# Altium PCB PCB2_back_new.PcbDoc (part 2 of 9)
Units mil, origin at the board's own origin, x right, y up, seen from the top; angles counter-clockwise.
Board outline 6299 x 3937 mil, 4 copper layers (TopLayer, GROUND, VCC, BottomLayer); 253 components, 421 nets, 2085 pads, 712 vias.
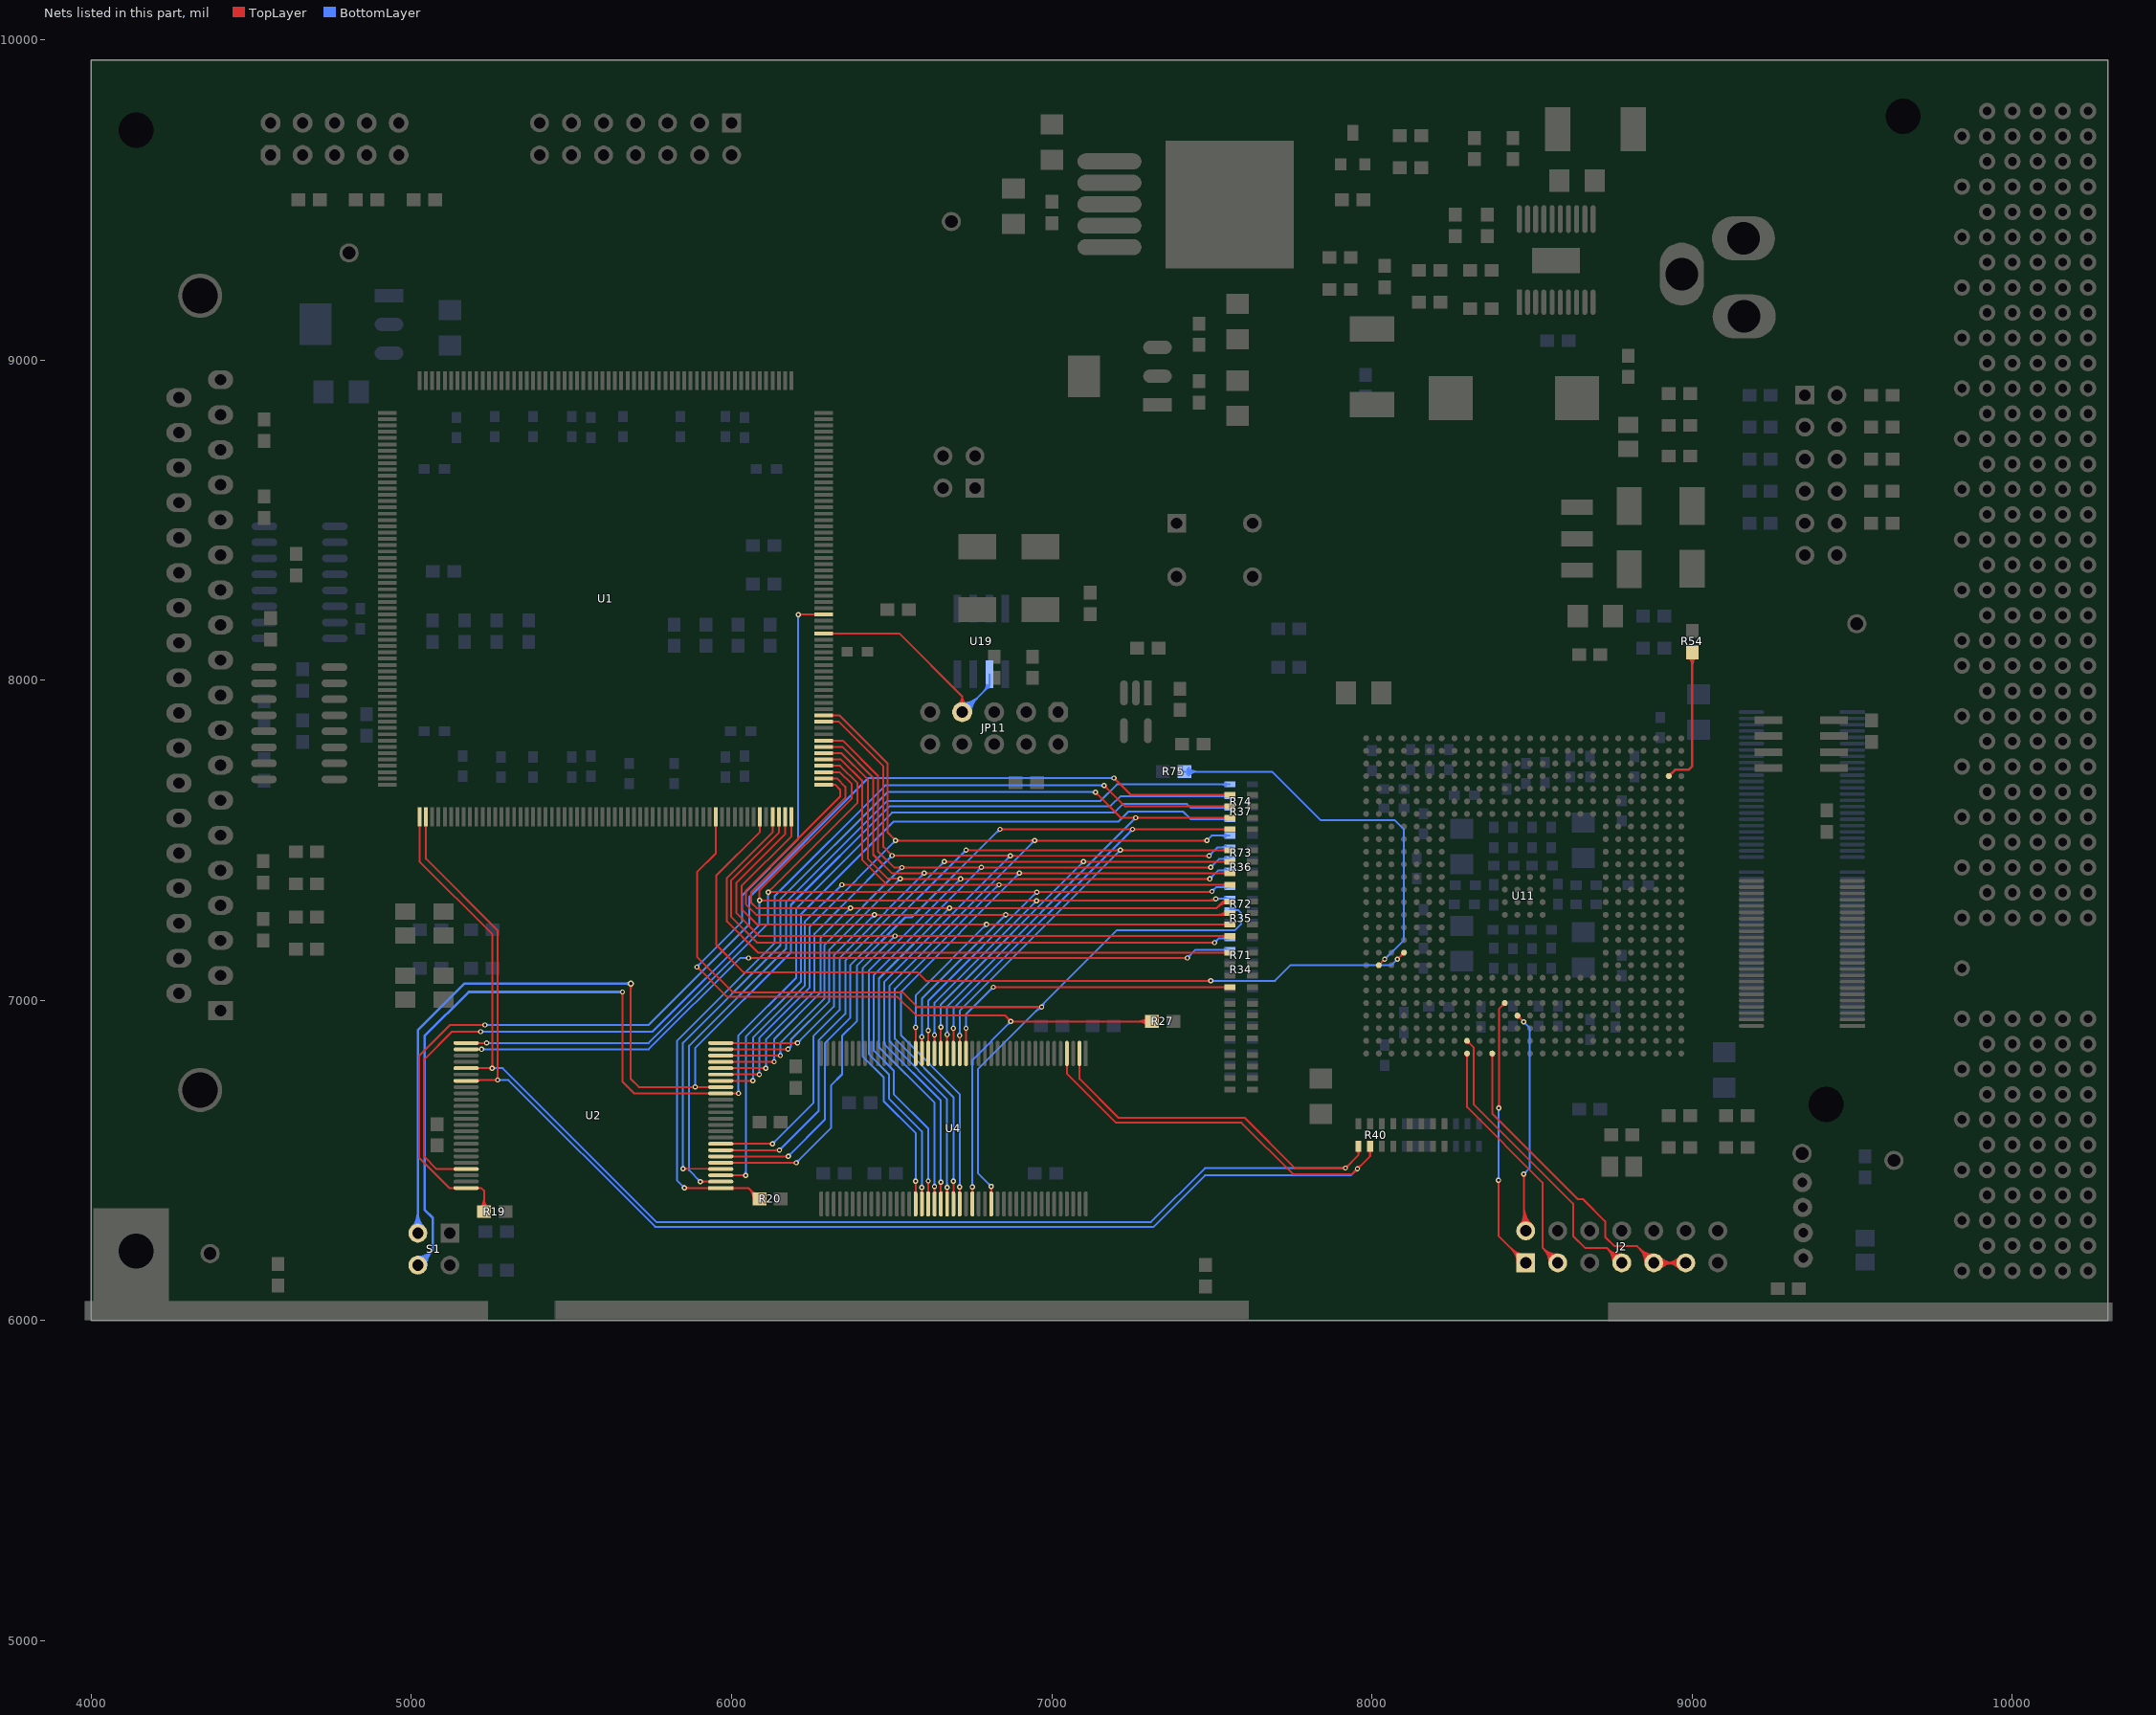
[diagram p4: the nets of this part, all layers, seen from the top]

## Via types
v1: diameter 16, hole 8, TopLayer to BottomLayer, 311 vias
v2: diameter 20, hole 10, TopLayer to BottomLayer, 202 vias
v3: diameter 24, hole 12, TopLayer to BottomLayer, 179 vias
v4: diameter 40, hole 20, TopLayer to BottomLayer, 12 vias
v5: diameter 30, hole 15, TopLayer to BottomLayer, 8 vias

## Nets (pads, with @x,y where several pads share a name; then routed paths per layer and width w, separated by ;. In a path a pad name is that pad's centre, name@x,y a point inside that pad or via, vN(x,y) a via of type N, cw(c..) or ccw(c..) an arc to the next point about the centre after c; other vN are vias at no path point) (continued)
BE1#: R72.6 U1.228 U4.71 | length 3283
  TopLayer w6: U1.228@5948.43,7547.22 cw(c5943.47,7542.26) 5950.49,7542.26 cw(c5957.5,7542.26) U1.228@5952.54,7547.22 ; U1.228@5950.49,7585.69 5950.49,7458.49 5892,7400 5892,7136 6003,7025 6534,7025 6580,6979 v1(6968,6979) ; v1@6807.19,6415.19 cw(c6798.65,6406.65) 6810.73,6406.65 cw(c6822.8,6406.65) v1@6814.26,6415.19 ; U4.71@6808.67,6399.52 ccw(c6803.71,6404.48) 6810.73,6404.48 ccw(c6817.74,6404.48) U4.71@6812.78,6399.52 ; U4.71@6810.73,6364 v1(6810.73,6418.73) ; v1@6964.46,6975.46 ccw(c6955.93,6966.93) 6955.93,6979 ccw(c6955.93,6991.07) v1@6964.46,6982.54
  BottomLayer w6: v1@6805.73,6418.73 ccw(c6793.65,6418.73) 6802.19,6427.26 ccw(c6810.73,6435.8) v1@6810.73,6423.72 ; v1@6816,6424 v1(6810.73,6418.73) 6770,6459.45 6770,6786 7203,7219 7572,7219 7591,7238 7591,7273 7582,7282 R72.6@7555.84,7282 ; 6950.93,6966.93 cw(c6968,6949.86) v1@6968,6974 ; v1@6973,6979 cw(c6997.14,6979) 6980.07,6996.07 ; R72.6@7568.59,7277.76 cw(c7578.83,7267.51) 7578.83,7282 cw(c7578.83,7296.49) R72.6@7568.59,7286.24
BE2#: R35.7 U1.240 U4.28 | length 2544.3
  TopLayer w6: U1.240@6184.65,7547.22 cw(c6179.69,7542.26) 6186.71,7542.26 cw(c6193.72,7542.26) U1.240@6188.76,7547.22 ; U1.240@6186.71,7585.69 6186.71,7512.71 6031,7357 6031,7285 6079,7237 R35.7@7555.84,7237 ; v1@6570.97,6911.97 cw(c6562.43,6903.43) 6574.51,6903.43 cw(c6586.58,6903.43) v1@6578.04,6911.97 ; U4.28@6572.45,6869.52 ccw(c6567.49,6874.48) 6574.51,6874.48 ccw(c6581.52,6874.48) U4.28@6576.56,6869.52 ; U4.28@6574.51,6834 v1(6574.51,6915.51) ; v1@6792.46,7233.46 ccw(c6783.93,7224.93) 6783.93,7237 ccw(c6783.93,7249.07) v1@6792.46,7240.54 ; v1@6799.54,7233.46 cw(c6808.07,7224.93) 6808.07,7237 cw(c6808.07,7249.07) v1@6799.54,7240.54 ; R35.7@7543.1,7232.76 ccw(c7532.86,7222.51) 7532.86,7237 ccw(c7532.86,7251.49) R35.7@7543.1,7241.24
  BottomLayer w6: v1@6570.97,6919.04 ccw(c6562.43,6927.58) 6574.51,6927.58 ccw(c6586.58,6927.58) v1@6578.04,6919.04 ; v1(6574.51,6915.51) 6574.51,7015.51 v1(6796,7237) ; v1@6791,7237 cw(c6778.93,7237) 6787.46,7228.46 cw(c6796,7219.93) v1@6796,7232
BE3#: R35.8 U1.239 U4.59 | length 3034.7
  TopLayer w6: U1.239@6164.97,7547.22 cw(c6160.01,7542.26) 6167.02,7542.26 cw(c6174.04,7542.26) U1.239@6169.08,7547.22 ; U1.239@6167.02,7585.69 6167.02,7519.02 6014,7366 6014,7273 6086,7201 R35.8@7555.84,7201 ; v1@6506.46,7197.46 ccw(c6497.93,7188.93) 6497.93,7201 ccw(c6497.93,7213.07) v1@6506.46,7204.54 ; v1@6513.54,7197.46 cw(c6522.07,7188.93) 6522.07,7201 cw(c6522.07,7213.07) v1@6513.54,7204.54 ; v1@6570.97,6431.97 cw(c6562.43,6423.43) 6574.51,6423.43 cw(c6586.58,6423.43) v1@6578.04,6431.97 ; U4.59@6572.45,6399.52 ccw(c6567.49,6404.48) 6574.51,6404.48 ccw(c6581.52,6404.48) U4.59@6576.56,6399.52 ; U4.59@6574.51,6364 v1(6574.51,6435.51) ; R35.8@7543.1,7196.76 ccw(c7532.86,7186.51) 7532.86,7201 ccw(c7532.86,7215.49) R35.8@7543.1,7205.24
  BottomLayer w6: v1@6505,7201 cw(c6492.93,7201) 6501.46,7192.46 cw(c6510,7183.93) v1@6510,7196 ; v1(6510,7201) 6409,7100 6409,6825 6475,6759 6475,6685 6574.51,6585.49 v1(6574.51,6435.51) ; v1@6570.97,6439.04 ccw(c6562.43,6447.58) 6574.51,6447.58 ccw(c6586.58,6447.58) v1@6578.04,6439.04
CE0#: R34.8 U4.20 | length 1090.7
  TopLayer w6: v1@6728.45,6908.78 cw(c6719.91,6900.24) 6731.98,6900.24 cw(c6744.06,6900.24) v1@6735.52,6908.78 ; U4.20@6729.93,6869.52 ccw(c6724.97,6874.48) 6731.99,6874.48 ccw(c6739,6874.48) U4.20@6734.04,6869.52 ; U4.20@6731.98,6834 v1(6731.98,6912.31) ; v1(6817,7041) R34.8@7555.84,7041 ; v1@6820.54,7037.46 cw(c6829.07,7028.93) 6829.07,7041 cw(c6829.07,7053.07) v1@6820.54,7044.54 ; R34.8@7543.1,7036.76 ccw(c7532.86,7026.51) 7532.86,7041 ccw(c7532.86,7055.49) R34.8@7543.1,7045.24
  BottomLayer w6: v1@6728.45,6915.85 ccw(c6719.91,6924.39) 6731.98,6924.39 ccw(c6744.06,6924.39) v1@6735.52,6915.85 ; v1(6731.98,6912.31) 6731.98,6955.98 v1(6817,7041) ; v1@6812,7041 cw(c6799.93,7041) 6808.46,7032.46 cw(c6817,7023.93) v1@6817,7036
CE1#: R71.7 U2.26 | length 2661.4
  TopLayer w6: U2.26@5170.72,6847.07 v1(5219,6847) ; U2.26@5206.24,6845.01 cw(c5211.08,6840.16) v1@5211.09,6847.01 ; U2.26@5206.25,6849.12 ccw(c5211.33,6854.19) v1@5211.32,6847.01 ; v1@5215.46,6843.47 ccw(c5206.91,6834.95) 5206.93,6847.02 ccw(c5206.95,6859.09) v1@5215.47,6850.54 ; v1(6053,7132) v1(7423,7132) ; v1@6056.54,7128.46 cw(c6065.07,7119.93) 6065.07,7132 cw(c6065.07,7144.07) v1@6056.54,7135.54 ; v1@7419.46,7128.46 ccw(c7410.93,7119.93) 7410.93,7132 ccw(c7410.93,7144.07) v1@7419.46,7135.54
  BottomLayer w6: v1(5219,6847) 5576.07,6847.07 5741.07,6847.07 6026,7132 v1(6053,7132) ; v1@5222.54,6843.47 cw(c5231.07,6834.93) 5231.07,6847 cw(c5231.07,6859.07) v1@5222.53,6850.54 ; v1@6049.46,7128.46 ccw(c6040.93,7119.93) 6040.93,7132 ccw(c6040.93,7144.07) v1@6049.46,7135.54 ; v1(7423,7132) 7449,7158 R71.7@7555.84,7158 ; v1@7423,7137 ccw(c7423,7149.07) 7431.54,7140.54 ccw(c7440.07,7132) v1@7428,7132 ; R71.7@7543.1,7153.76 ccw(c7532.86,7143.51) 7532.86,7158 ccw(c7532.86,7172.49) R71.7@7543.1,7162.24
CE2#: R71.8 U1.238 | length 2054.9
  TopLayer w6: U1.238@6145.28,7547.22 cw(c6140.32,7542.26) 6147.34,7542.26 cw(c6154.35,7542.26) U1.238@6149.39,7547.22 ; U1.238@6147.34,7585.69 6147.34,7523.34 5998,7374 5998,7262 6080,7180 v1(7508,7180) ; v1@7504.46,7176.46 ccw(c7495.93,7167.93) 7495.93,7180 ccw(c7495.93,7192.07) v1@7504.46,7183.54
  BottomLayer w6: v1(7508,7180) 7522,7194 R71.8@7555.84,7194 ; v1@7508,7185 ccw(c7508,7197.07) 7516.54,7188.54 ccw(c7525.07,7180) v1@7513,7180 ; R71.8@7543.1,7189.76 ccw(c7532.86,7179.51) 7532.86,7194 ccw(c7532.86,7208.49) R71.8@7543.1,7198.24
CE3#: R34.5 U1.237 | length 2043.6
  TopLayer w6: U1.237@6125.6,7547.22 cw(c6120.64,7542.26) 6127.65,7542.26 cw(c6134.67,7542.26) U1.237@6129.71,7547.22 ; U1.237@6127.65,7585.69 6127.65,7524.65 5985,7382 5985,7246 6082,7149 R34.5@7555.84,7149 ; R34.5@7543.1,7144.76 ccw(c7532.86,7134.51) 7532.86,7149 ccw(c7532.86,7163.49) R34.5@7543.1,7153.24
DATA: JP11.7 U1.25 U19.2 | length 1133
  TopLayer w6: U1.25@6287.1,8145.73 6523.27,8145.73 6720,7949 ; U1.25@6312.78,8143.68 cw(c6317.74,8138.72) 6317.74,8145.73 cw(c6317.74,8152.75) U1.25@6312.78,8147.79 ; JP11.7@6705.79,7924.12 ccw(c6691.13,7949) 6720,7949 ; JP11.7@6708.83,7918.95 ccw(c6697.32,7938.5) 6720,7938.5 ccw(c6742.68,7938.5) JP11.7@6731.17,7918.95 ; JP11.7@6720,7900 6720,7949 ; JP11.7@6734.21,7924.12 cw(c6748.87,7949) 6720,7949
  BottomLayer w6: JP11.7@6720,7900 6723,7900 6805,7982 U19.2@6805,8017.64 ; JP11.7@6720,7916 ccw(c6720,7961.87) 6752.44,7929.44 ; JP11.7@6720,7922 ccw(c6720,7982.36) 6762.68,7939.68 ; JP11.7@6720,7928 ccw(c6720,8002.84) 6772.92,7949.92 ; JP11.7@6736,7900 cw(c6767.38,7900) 6745.19,7922.19 ; JP11.7@6742,7900 cw(c6787.87,7900) 6755.44,7932.44 ; JP11.7@6748,7900 cw(c6808.36,7900) 6765.68,7942.68 ; 6787.03,7964.03 ccw(c6764.92,7986.14) U19.2@6796.19,7986.14 ; 6797.03,7974.03 cw(c6805,7966.06) U19.2@6805,7977.33 ; 6797.27,7974.27 ccw(c6785.4,7986.14) U19.2@6802.19,7986.14
DSP_CLKIN: R54.2 U11.AC2 | length 521.1
  TopLayer w8: U11.AC2@8926.63,7700.14 8946.49,7720 8989,7720 9000,7731 R54.2@9000,8086.54 ; U11.AC2@8926.63,7705.39 ccw(c8926.63,7718.07) 8935.6,7709.11 ccw(c8944.56,7700.14) U11.AC2@8931.88,7700.14 ; R54.2@8988.91,8073.48 cw(c8962.13,8046.7) 9000,8046.7 cw(c9037.87,8046.7) R54.2@9011.09,8073.48
DSP_T\R\S\T\: J2.2 U11.D14 | length 1013.7
  TopLayer w6: U11.D14@8454.19,6945.86 cw(c8454.19,6930.77) 8464.86,6941.44 cw(c8475.53,6952.11) U11.D14@8460.44,6952.11 ; U11.D14@8454.19,6952.11 v1(8474,6932.3) ; J2.2@8461.24,6298.76 ccw(c8430.44,6329.56) 8474,6329.56 ccw(c8529.56,6329.56) J2.2@8490.27,6290.27 ; J2.2@8465.48,6294.52 ccw(c8444.93,6315.07) 8474,6315.07 ccw(c8515.07,6315.07) J2.2@8486.03,6286.03 ; v1@8470.46,6453.46 cw(c8461.93,6444.93) 8474,6444.93 cw(c8486.07,6444.93) v1@8477.54,6453.46 ; 8474,6344.04 ccw(c8544.04,6344.04) J2.2@8494.52,6294.52 ; 8474,6358.53 ccw(c8558.53,6358.53) J2.2@8498.76,6298.76 ; v1(8474,6457) 8474,6286 J2.2@8480,6280
  BottomLayer w6: v1(8474,6457) 8492,6475 8492,6914.3 v1(8474,6932.3) ; v1@8474,6462 ccw(c8474,6474.07) 8482.54,6465.54 ccw(c8491.07,6457) v1@8479,6457
DSP_TCLK: J2.9 J2.11 U11.A16 | length 1738.3
  TopLayer w6: U11.A16@8371.03,6829.58 cw(c8360.36,6818.91) 8375.45,6818.91 cw(c8390.54,6818.91) U11.A16@8379.87,6829.58 ; U11.A16@8375.45,6834 8375.45,6646.55 8643,6379 8659,6379 8728,6310 8728,6261 8757,6232 8828,6232 J2.9@8880,6180 J2.11@8980,6180 ; J2.9@8853.47,6180 ccw(c8789.43,6180) 8834.71,6225.29 ccw(c8880,6270.57) J2.9@8880,6206.53 ; J2.9@8859.47,6180 ccw(c8809.91,6180) 8844.96,6215.04 ccw(c8880,6250.09) J2.9@8880,6200.53 ; J2.9@8865.47,6180 ccw(c8830.4,6180) 8855.2,6204.8 ccw(c8880,6229.6) J2.9@8880,6194.53 ; J2.9@8890.27,6169.73 cw(c8915.07,6144.93) 8915.07,6180 cw(c8915.07,6215.07) J2.9@8890.27,6190.27 ; J2.9@8894.52,6165.48 cw(c8929.56,6130.44) 8929.56,6180 cw(c8929.56,6229.56) J2.9@8894.52,6194.52 ; J2.9@8898.76,6161.24 cw(c8944.04,6115.96) 8944.04,6180 cw(c8944.04,6244.04) J2.9@8898.76,6198.76 ; J2.11@8961.24,6161.24 ccw(c8915.96,6115.96) 8915.96,6180 ccw(c8915.96,6244.04) J2.11@8961.24,6198.76 ; J2.11@8965.48,6165.48 ccw(c8930.44,6130.44) 8930.44,6180 ccw(c8930.44,6229.56) J2.11@8965.48,6194.52 ; J2.11@8969.73,6169.73 ccw(c8944.93,6144.93) 8944.93,6180 ccw(c8944.93,6215.07) J2.11@8969.73,6190.27
DSP_TDI: J2.3 U11.A18 | length 1028.6
  TopLayer w6: U11.A18@8292.29,6829.58 cw(c8281.61,6818.91) 8296.71,6818.91 cw(c8311.8,6818.91) U11.A18@8301.13,6829.58 ; U11.A18@8296.71,6834 8296.71,6666.29 8532,6431 8532,6228 J2.3@8580,6180 ; J2.3@8553.47,6180 ccw(c8489.43,6180) 8534.71,6225.29 ccw(c8580,6270.57) J2.3@8580,6206.53 ; J2.3@8559.47,6180 ccw(c8509.91,6180) 8544.96,6215.04 ccw(c8580,6250.09) J2.3@8580,6200.53 ; J2.3@8565.47,6180 ccw(c8530.4,6180) 8555.2,6204.8 ccw(c8580,6229.6) J2.3@8580,6194.53
DSP_TDO: J2.7 U11.B18 | length 1190.6
  TopLayer w6: U11.B18@8296.71,6867.12 cw(c8296.71,6852.02) 8307.38,6862.7 cw(c8318.05,6873.37) U11.B18@8302.96,6873.37 ; U11.B18@8296.71,6873.37 8317,6853.08 8317,6676 8628,6365 8628,6264 8666,6226 8734,6226 J2.7@8780,6180 ; J2.7@8753.47,6180 ccw(c8689.43,6180) 8734.71,6225.29 ccw(c8780,6270.57) J2.7@8780,6206.53 ; J2.7@8759.47,6180 ccw(c8709.91,6180) 8744.96,6215.04 ccw(c8780,6250.09) J2.7@8780,6200.53 ; J2.7@8765.47,6180 ccw(c8730.4,6180) 8755.2,6204.8 ccw(c8780,6229.6) J2.7@8780,6194.53
DSP_TMS: J2.1 U11.E15 | length 1188
  TopLayer w6: v1@8391.46,6434.46 cw(c8382.93,6425.93) 8395,6425.93 cw(c8407.07,6425.93) v1@8398.54,6434.46 ; v1@8392.46,6667.54 ccw(c8383.93,6676.07) 8396,6676.07 ccw(c8408.07,6676.07) v1@8399.54,6667.54 ; v1(8395,6438) 8395,6265 J2.1@8480,6180 ; v1(8396,6664) 8396,6972.66 U11.E15@8414.82,6991.48 ; U11.E15@8408.57,6991.48 cw(c8393.47,6991.48) 8404.15,6980.81 cw(c8414.82,6970.14) U11.E15@8414.82,6985.23 ; J2.1@8453.47,6180 ccw(c8389.43,6180) 8434.71,6225.29 ccw(c8480,6270.57) J2.1@8480,6206.53 ; J2.1@8459.47,6180 ccw(c8409.91,6180) 8444.96,6215.04 ccw(c8480,6250.09) J2.1@8480,6200.53 ; J2.1@8465.47,6180 ccw(c8430.4,6180) 8455.2,6204.8 ccw(c8480,6229.6) J2.1@8480,6194.53
  BottomLayer w6: v1@8391.46,6441.54 ccw(c8382.93,6450.07) 8395,6450.07 ccw(c8407.07,6450.07) v1@8398.54,6441.54 ; v1@8392.46,6660.46 cw(c8386.34,6654.34) 8395,6654.34 ; v1(8395,6438) 8395,6663 v1(8396,6664) ; 8395,6649.51 cw(c8410.49,6649.51) v1@8399.54,6660.46
EA03: R72.7 U1.3 U2.45 U4.25 | length 4739.6
  TopLayer w6: U2.45@5135.21,6471 ccw(c5130.25,6466.04) 5130.25,6473.06 ccw(c5130.25,6480.07) U2.45@5135.21,6475.11 ; U2.45@5170.72,6473.06 5078.94,6473.06 5039,6513 5039,6815 5126,6902 v1(5216,6902) ; v1@5212.46,6898.46 ccw(c5203.93,6889.93) 5203.93,6902 ccw(c5203.93,6914.07) v1@5212.46,6905.54 ; v1@6083.46,7315.54 ccw(c6074.93,7324.07) 6087,7324.07 ccw(c6099.07,7324.07) 6090.54,7315.54 ccw(c6101.49,7326.49) 6101.49,7311 ; v1(6087,7312) 6087,7343 6375,7631 6375,7675 6337.34,7712.66 U1.3@6274.31,7712.66 ; v1@6088,7311 7506,7311 ; v1@6090.54,7308.46 cw(c6096.66,7302.34) 6096.66,7311 ; U1.3@6312.78,7710.61 cw(c6317.74,7705.65) 6317.74,7712.66 cw(c6317.74,7719.68) U1.3@6312.78,7714.72 ; v1@6630.02,6888.02 cw(c6621.49,6879.49) 6633.56,6879.49 cw(c6645.63,6879.49) v1@6637.1,6888.02 ; U4.25@6631.51,6869.52 ccw(c6626.55,6874.48) 6633.56,6874.48 ccw(c6640.57,6874.48) U4.25@6635.61,6869.52 ; U4.25@6633.56,6834 v1(6633.56,6891.56) ; v1@6948.46,7307.46 ccw(c6939.93,7298.93) 6939.93,7311 ccw(c6939.93,7323.07) v1@6948.46,7314.54 ; v1@6955.54,7307.46 cw(c6964.07,7298.93) 6964.07,7311 cw(c6964.07,7323.07) v1@6955.54,7314.54 ; 7485.44,7311 ccw(c7485.44,7343.56) v1@7508.46,7320.54 ; 7499.93,7311 ccw(c7499.93,7329.07) v1@7512.71,7316.29 ; v1@7507.19,7315.62 cw(c7502.68,7314.32) 7506,7311 ; v1@7510.62,7312.19 ccw(c7509.32,7307.68) 7506,7311 ; v1(7512,7317) 7506,7311
  BottomLayer w6: v1(5216,6902) 5753,6902 6087,7236 v1(6087,7312) ; v1@5219.54,6898.46 cw(c5228.07,6889.93) 5228.07,6902 cw(c5228.07,6914.07) v1@5219.54,6905.54 ; v1@6083.46,7308.46 cw(c6074.93,7299.93) 6087,7299.93 cw(c6099.07,7299.93) v1@6090.54,7308.46 ; v1@6630.02,6895.1 ccw(c6621.49,6903.63) 6633.56,6903.63 ccw(c6645.63,6903.63) v1@6637.1,6895.1 ; v1(6633.56,6891.56) 6633.56,6992.56 v1(6952,7311) ; v1@6947,7311 cw(c6934.93,7311) 6943.46,7302.46 cw(c6952,7293.93) v1@6952,7306 ; v1(7512,7317) R72.7@7554.84,7317 ; v1@7515.54,7313.46 cw(c7524.07,7304.93) 7524.07,7317 cw(c7524.07,7329.07) v1@7515.54,7320.54 ; 7530.44,7317 ccw(c7530.44,7334.9) R72.7@7543.1,7322.24 ; 7535.27,7317 cw(c7535.27,7305.93) R72.7@7543.1,7313.76
EA04: R72.8 U1.4 U2.25 U4.26 | length 4164.8
  TopLayer w6: U2.25@5170.72,6866.76 v1(5234.76,6866.76) ; U2.25@5206.24,6864.7 cw(c5211.2,6859.74) 5211.2,6866.76 cw(c5211.2,6873.77) U2.25@5206.24,6868.81 ; v1@5231.22,6863.22 ccw(c5222.68,6854.68) 5222.68,6866.76 ccw(c5222.68,6878.83) v1@5231.22,6870.29 ; v1@6114,7343 ccw(c6114,7355.07) 6122.54,7346.54 ccw(c6131.07,7338) v1@6119,7338 ; v1@6117.54,7334.46 cw(c6126.07,7325.93) 6126.07,7338 cw(c6126.07,7350.07) v1@6117.54,7341.54 ; U1.4@6274.31,7732.35 6338.65,7732.35 6393,7678 6393,7617 v1(6114,7338) 7498,7338 v1(7500,7340) ; U1.4@6312.78,7730.29 cw(c6317.74,7725.33) 6317.74,7732.35 cw(c6317.74,7739.36) U1.4@6312.78,7734.4 ; v1@6610.34,6901.78 cw(c6601.8,6893.24) 6613.88,6893.24 cw(c6625.95,6893.24) v1@6617.41,6901.78 ; U4.26@6611.82,6869.52 ccw(c6606.86,6874.48) 6613.88,6874.48 ccw(c6620.89,6874.48) U4.26@6615.93,6869.52 ; U4.26@6613.88,6834 v1(6613.88,6905.31) ; v1@6949.46,7334.46 ccw(c6940.93,7325.93) 6940.93,7338 ccw(c6940.93,7350.07) v1@6949.46,7341.54 ; v1@6956.54,7334.46 cw(c6965.07,7325.93) 6965.07,7338 cw(c6965.07,7350.07) v1@6956.54,7341.54 ; 7483.1,7338 ccw(c7483.1,7356.9) v1@7496.46,7343.54
  BottomLayer w6: v1(5234.76,6866.76) 5740.76,6866.76 6114,7240 v1(6114,7338) ; v1@5238.29,6863.22 cw(c5246.83,6854.68) 5246.83,6866.76 cw(c5246.83,6878.83) v1@5238.29,6870.29 ; v1@6110.46,7334.46 cw(c6101.93,7325.93) 6114,7325.93 cw(c6126.07,7325.93) v1@6117.54,7334.46 ; v1@6610.34,6908.85 ccw(c6601.8,6917.39) 6613.88,6917.39 ccw(c6625.95,6917.39) v1@6617.41,6908.85 ; v1(6613.88,6905.31) 6613.88,6998.88 v1(6953,7338) ; v1@6948,7338 cw(c6935.93,7338) 6944.46,7329.46 cw(c6953,7320.93) v1@6953,7333 ; v1(7500,7340) 7514,7354 R72.8@7555.84,7354 ; v1@7500,7345 ccw(c7500,7357.07) 7508.54,7348.54 ccw(c7517.07,7340) v1@7505,7340 ; R72.8@7543.1,7349.76 ccw(c7532.86,7339.51) 7532.86,7354 ccw(c7532.86,7368.49) R72.8@7543.1,7358.24
EA05: R35.6 U1.1 U2.24 U4.27 | length 3625.6
  TopLayer w6: U2.24@5966,6866.76 v1(6205.76,6866.76) ; U2.24@6001.52,6864.7 cw(c6006.48,6859.74) 6006.48,6866.76 cw(c6006.48,6873.77) U2.24@6001.52,6868.81 ; v1@6202.22,6863.22 ccw(c6193.68,6854.68) 6193.68,6866.76 ccw(c6193.68,6878.83) v1@6202.22,6870.29 ; U1.1@6274.31,7673.29 6323.71,7673.29 6339,7658 6339,7637 6045,7343 6045,7299 6077,7267 7549.84,7267 R35.6@7555.84,7273 ; U1.1@6312.78,7671.24 cw(c6317.74,7666.28) 6317.74,7673.29 cw(c6317.74,7680.31) U1.1@6312.78,7675.35 ; v1@6442.46,7263.46 ccw(c6433.93,7254.93) 6433.93,7267 ccw(c6433.93,7279.07) v1@6442.46,7270.54 ; v1@6449.54,7263.46 cw(c6458.07,7254.93) 6458.07,7267 cw(c6458.07,7279.07) v1@6449.54,7270.54 ; v1@6590.65,6882.09 cw(c6582.12,6873.56) 6594.19,6873.56 cw(c6606.26,6873.56) v1@6597.73,6882.09 ; U4.27@6592.14,6869.52 ccw(c6587.18,6874.48) 6594.19,6874.48 ccw(c6601.2,6874.48) U4.27@6596.24,6869.52 ; U4.27@6594.19,6834 v1(6594.19,6885.63) ; v1@6852.46,7263.46 ccw(c6843.93,7254.93) 6843.93,7267 ccw(c6843.93,7279.07) v1@6852.46,7270.54 ; v1@6859.54,7263.46 cw(c6868.07,7254.93) 6868.07,7267 cw(c6868.07,7279.07) v1@6859.54,7270.54 ; 7518.37,7267 ccw(c7518.37,7301.97) R35.6@7543.1,7277.24 ; 7532.86,7267 ccw(c7532.86,7287.49) R35.6@7547.34,7273
  BottomLayer w6: v1(6205.76,6866.76) 6319,6980 6319,7140 v1(6446,7267) ; v1@6205.76,6871.76 ccw(c6205.76,6883.83) 6214.29,6875.29 ccw(c6222.83,6866.76) v1@6210.76,6866.76 ; v1@6441,7267 cw(c6428.93,7267) 6437.46,7258.46 cw(c6446,7249.93) v1@6446,7262 ; v1@6590.65,6889.17 ccw(c6582.12,6897.7) 6594.19,6897.7 ccw(c6606.26,6897.7) v1@6597.73,6889.17 ; v1(6594.19,6885.63) 6594.19,7005.19 v1(6856,7267) ; v1@6851,7267 cw(c6838.93,7267) 6847.46,7258.46 cw(c6856,7249.93) v1@6856,7262
EA06: R73.5 U1.6 U2.23 U4.60 | length 3974.6
  TopLayer w6: U2.23@5966,6847.07 v1(6176.07,6847.07) ; U2.23@6001.52,6845.02 cw(c6006.48,6840.06) 6006.48,6847.07 cw(c6006.48,6854.08) U2.23@6001.52,6849.12 ; v1@6172.53,6843.53 ccw(c6164,6835) 6164,6847.07 ccw(c6164,6859.14) v1@6172.53,6850.61 ; U1.6@6274.31,7771.72 6343.28,7771.72 6425,7690 6425,7442 6487.1,7379.9 v1(6526.9,7379.9) ; U1.6@6312.78,7769.66 cw(c6317.74,7764.7) 6317.74,7771.72 cw(c6317.74,7778.73) U1.6@6312.78,7773.77 ; v1@6523.37,7376.37 ccw(c6514.83,7367.83) 6514.83,7379.9 ccw(c6514.83,7391.98) v1@6523.37,7383.44 ; v1@6526.9,7379 v1(7493,7379) ; v1@6530.44,7376.37 cw(c6536.79,7370.02) 6536.79,7379 ; v1@6530.44,7383.44 ccw(c6541.16,7394.16) 6541.16,7379 ; v1@6590.65,6411.65 cw(c6582.12,6403.12) 6594.19,6403.12 cw(c6606.26,6403.12) v1@6597.73,6411.65 ; U4.60@6592.14,6399.52 ccw(c6587.18,6404.48) 6594.19,6404.48 ccw(c6601.2,6404.48) U4.60@6596.24,6399.52 ; U4.60@6594.19,6364 v1(6594.19,6415.19) ; v1@6711.46,7375.46 ccw(c6702.93,7366.93) 6702.93,7379 ccw(c6702.93,7391.07) v1@6711.46,7382.54 ; v1@6718.54,7375.46 cw(c6727.07,7366.93) 6727.07,7379 cw(c6727.07,7391.07) v1@6718.54,7382.54 ; v1@7489.46,7375.46 ccw(c7480.93,7366.93) 7480.93,7379 ccw(c7480.93,7391.07) v1@7489.46,7382.54
  BottomLayer w6: v1(6176.07,6847.07) 6185,6856 6185,6877 6305,6997 6305,7158 v1(6526.9,7379.9) ; v1@6176.07,6852.07 ccw(c6176.07,6864.14) 6184.61,6855.61 ccw(c6193.14,6847.07) v1@6181.07,6847.07 ; v1@6521.9,7379.9 cw(c6509.83,7379.9) 6518.37,7371.37 cw(c6526.9,7362.83) v1@6526.9,7374.9 ; v1@6590.65,6418.73 ccw(c6582.12,6427.26) 6594.19,6427.26 ccw(c6606.26,6427.26) v1@6597.73,6418.73 ; v1(6594.19,6415.19) 6594.19,6591 6491,6694.19 6491,6769 6428,6832 6428,7092 v1(6715,7379) ; v1@6710,7379 cw(c6697.93,7379) 6706.46,7370.46 cw(c6715,7361.93) v1@6715,7374 ; v1(7493,7379) 7520,7406 R73.5@7555.84,7406 ; v1@7493,7384 ccw(c7493,7396.07) 7501.54,7387.54 ccw(c7510.07,7379) v1@7498,7379 ; R73.5@7543.1,7401.76 ccw(c7532.86,7391.51) 7532.86,7406 ccw(c7532.86,7420.49) R73.5@7543.1,7410.24
EA07: R73.6 U1.8 U2.22 U4.61 | length 4070
  TopLayer w6: U2.22@5966,6827.39 v1(6152.39,6827.39) ; U2.22@6001.52,6825.33 cw(c6006.48,6820.37) 6006.48,6827.39 cw(c6006.48,6834.4) U2.22@6001.52,6829.44 ; v1@6148.85,6823.85 ccw(c6140.31,6815.31) 6140.31,6827.39 ccw(c6140.31,6839.46) v1@6148.85,6830.92 ; U1.8@6274.31,7811.09 6346.91,7811.09 6457,7701 6457,7465 6507.19,7414.81 v1(6531.81,7414.81) ; U1.8@6312.78,7809.03 cw(c6317.74,7804.07) 6317.74,7811.09 cw(c6317.74,7818.1) U1.8@6312.78,7813.14 ; v1@6528.28,7411.28 ccw(c6519.74,7402.74) 6519.74,7414.81 ccw(c6519.74,7426.89) v1@6528.28,7418.35 ; v1@6531.81,7415 v1(7496,7415) ; v1@6535.35,7411.28 cw(c6544.33,7402.3) 6544.33,7415 ; v1@6535.35,7418.35 ccw(c6543.44,7426.44) 6543.44,7415 ; v1@6610.34,6432.34 cw(c6601.8,6423.8) 6613.88,6423.8 cw(c6625.95,6423.8) v1@6617.41,6432.34 ; U4.61@6611.82,6399.52 ccw(c6606.86,6404.48) 6613.88,6404.48 ccw(c6620.89,6404.48) U4.61@6615.93,6399.52 ; U4.61@6613.88,6364 v1(6613.88,6435.88) ; v1@6776.46,7411.46 ccw(c6767.93,7402.93) 6767.93,7415 ccw(c6767.93,7427.07) v1@6776.46,7418.54 ; v1@6783.54,7411.46 cw(c6792.07,7402.93) 6792.07,7415 cw(c6792.07,7427.07) v1@6783.54,7418.54 ; v1@7492.46,7411.46 ccw(c7483.93,7402.93) 7483.93,7415 ccw(c7483.93,7427.07) v1@7492.46,7418.54
  BottomLayer w6: v1@6148.85,6830.92 ccw(c6140.31,6839.46) 6152.39,6839.46 ccw(c6164.46,6839.46) v1@6155.92,6830.92 ; v1(6152.39,6827.39) 6152.39,6868.39 6290,7006 6290,7173 v1(6531.81,7414.81) ; v1@6526.81,7414.81 cw(c6514.74,7414.81) 6523.28,7406.28 cw(c6531.81,7397.74) v1@6531.81,7409.81 ; v1@6610.34,6439.41 ccw(c6601.8,6447.95) 6613.88,6447.95 ccw(c6625.95,6447.95) v1@6617.41,6439.41 ; v1(6613.88,6435.88) 6613.88,6599 6506,6706.88 6506,6781 6444,6843 6444,7079 v1(6780,7415) ; v1@6775,7415 cw(c6762.93,7415) 6771.46,7406.46 cw(c6780,7397.93) v1@6780,7410 ; v1(7496,7415) 7523,7442 R73.6@7555.84,7442 ; v1@7496,7420 ccw(c7496,7432.07) 7504.54,7423.54 ccw(c7513.07,7415) v1@7501,7415 ; R73.6@7543.1,7437.76 ccw(c7532.86,7427.51) 7532.86,7442 ccw(c7532.86,7456.49) R73.6@7543.1,7446.24
EA08: R35.5 U1.2 U2.21 U4.62 | length 4238.6
  TopLayer w6: U2.21@5966,6807.7 v1(6132.7,6807.7) ; U2.21@6001.52,6805.65 cw(c6006.48,6800.69) 6006.48,6807.7 cw(c6006.48,6814.71) U2.21@6001.52,6809.75 ; v1@6129.16,6804.16 ccw(c6120.63,6795.63) 6120.63,6807.7 ccw(c6120.63,6819.77) v1@6129.16,6811.24 ; U1.2@6274.31,7692.98 6329.02,7692.98 6355,7667 6355,7632 6061,7338 6061,7305 6078,7288 7515,7288 7536,7309 ; U1.2@6312.78,7690.92 cw(c6317.74,7685.96) 6317.74,7692.98 cw(c6317.74,7699.99) U1.2@6312.78,7695.03 ; v1@6367.46,7284.46 ccw(c6358.93,7275.93) 6358.93,7288 ccw(c6358.93,7300.07) v1@6367.46,7291.54 ; v1@6374.54,7284.46 cw(c6383.07,7275.93) 6383.07,7288 cw(c6383.07,7300.07) v1@6374.54,7291.54 ; v1@6630.02,6415.02 cw(c6621.49,6406.49) 6633.56,6406.49 cw(c6645.63,6406.49) v1@6637.1,6415.02 ; U4.62@6631.51,6399.52 ccw(c6626.55,6404.48) 6633.56,6404.48 ccw(c6640.57,6404.48) U4.62@6635.61,6399.52 ; U4.62@6633.56,6364 v1(6633.56,6418.56) ; v1@6676.46,7284.46 ccw(c6667.93,7275.93) 6667.93,7288 ccw(c6667.93,7300.07) v1@6676.46,7291.54 ; v1@6683.54,7284.46 cw(c6692.07,7275.93) 6692.07,7288 cw(c6692.07,7300.07) v1@6683.54,7291.54 ; 7517.74,7290.74 cw(c7547.34,7261.13) R35.5@7547.34,7303 ; 7527.98,7300.98 cw(c7547.34,7281.62) 7547.34,7309 ccw(c7541.73,7301.64) 7535.18,7308.18 ; 7530.33,7303.33 cw(c7537.53,7296.13) R35.5@7543.71,7304.23 ; R35.5@7542.38,7305.62 ccw(c7536,7301.28) 7536,7309 ; R35.5@7542.38,7312.38 cw(c7536,7316.72) 7536,7309 ; R35.5@7555.84,7309 7536,7309
  BottomLayer w6: v1@6129.16,6811.24 ccw(c6120.63,6819.77) 6132.7,6819.77 ccw(c6144.77,6819.77) v1@6136.24,6811.24 ; v1(6132.7,6807.7) 6132.7,6879 6277,7023.3 6277,7194 v1(6371,7288) ; v1@6366,7288 cw(c6353.93,7288) 6362.46,7279.46 cw(c6371,7270.93) v1@6371,7283 ; v1@6630.02,6422.1 ccw(c6621.49,6430.63) 6633.56,6430.63 ccw(c6645.63,6430.63) v1@6637.1,6422.1 ; v1(6633.56,6418.56) 6633.56,6680.44 6460,6854 6460,7068 v1(6680,7288) ; v1@6675,7288 cw(c6662.93,7288) 6671.46,7279.46 cw(c6680,7270.93) v1@6680,7283
EA09: R73.7 U1.11 U2.20 U4.63 | length 4196.4
  TopLayer w6: U2.20@5966,6788.02 v1(6107.02,6788.02) ; U2.20@6001.52,6785.96 cw(c6006.48,6781) 6006.48,6788.02 cw(c6006.48,6795.03) U2.20@6001.52,6790.07 ; v1@6103.48,6784.48 ccw(c6094.94,6775.94) 6094.94,6788.02 ccw(c6094.94,6800.09) v1@6103.48,6791.55 ; U1.11@6274.31,7870.14 6334.86,7870.14 6474,7731 6474,7479 v1(6501,7452) 6870,7451.63 v1(7491,7451) ; U1.11@6312.78,7868.09 cw(c6317.74,7863.13) 6317.74,7870.14 cw(c6317.74,7877.16) U1.11@6312.78,7872.2 ; v1@6496,7452 ccw(c6483.93,7452) 6492.46,7460.54 ccw(c6501,7469.07) v1@6501,7457 ; v1@6504.53,7448.46 cw(c6513.06,7439.92) 6513.07,7451.99 cw(c6513.08,7464.06) v1@6504.54,7455.53 ; v1@6649.71,6428.22 cw(c6641.17,6419.68) 6653.24,6419.68 cw(c6665.32,6419.68) v1@6656.78,6428.22 ; U4.63@6651.19,6399.52 ccw(c6646.23,6404.48) 6653.24,6404.48 ccw(c6660.26,6404.48) U4.63@6655.3,6399.52 ; U4.63@6653.24,6364 v1(6653.24,6431.76) ; 6856.42,7451.64 cw(c6856.4,7437.43) v1@6866.46,7447.47 ; 6859.44,7451.64 ccw(c6859.45,7461.57) v1@6866.47,7454.54 ; v1@6873.53,7447.46 cw(c6883.57,7437.4) 6883.59,7451.61 ; v1@6873.54,7454.53 ccw(c6880.57,7461.55) 6880.56,7451.62 ; v1@7487.46,7447.47 ccw(c7478.92,7438.94) 7478.93,7451.01 ccw(c7478.94,7463.08) v1@7487.47,7454.54
  BottomLayer w6: v1@6103.48,6791.55 ccw(c6094.94,6800.09) 6107.02,6800.09 ccw(c6119.09,6800.09) v1@6110.55,6791.55 ; v1(6107.02,6788.02) 6107.02,6878.02 6259,7030 6259,7208 6342,7291 ; 6341.2,7291.8 v1(6501,7452) ; v1@6496,7451.99 cw(c6483.93,7451.98) 6492.48,7443.45 cw(c6501.02,7434.93) v1@6501.01,7447 ; v1@6649.71,6435.29 ccw(c6641.17,6443.83) 6653.24,6443.83 ccw(c6665.32,6443.83) v1@6656.78,6435.29 ; v1(6653.24,6431.76) 6653.24,6686.76 6477,6863 6477,7058 v1(6870,7451) ; v1@6865,7451 cw(c6852.93,7451) 6861.46,7442.46 cw(c6870,7433.93) v1@6870,7446 ; v1(7491,7451) 7518,7478 R73.7@7565,7478 ; v1@7491,7456 ccw(c7491,7468.07) 7499.54,7459.54 ccw(c7508.07,7451) v1@7496,7451 ; R73.7@7543.1,7473.76 ccw(c7532.86,7463.51) 7532.86,7478 ccw(c7532.86,7492.49) R73.7@7543.1,7482.24
EA10: R73.8 U1.12 U2.19 U4.64 | length 4283.7
  TopLayer w6: U2.19@5966,6768.33 v1(6086.33,6768.33) ; U2.19@6001.52,6766.28 cw(c6006.48,6761.32) 6006.48,6768.33 cw(c6006.48,6775.34) U2.19@6001.52,6770.38 ; v1@6082.79,6764.79 ccw(c6074.26,6756.26) 6074.26,6768.33 ccw(c6074.26,6780.4) v1@6082.79,6771.87 ; U1.12@6274.31,7889.83 6337.17,7889.83 6487,7740 6487,7524 v1(6512,7499) v1(7484,7499) ; U1.12@6312.78,7887.77 cw(c6317.74,7882.81) 6317.74,7889.83 cw(c6317.74,7896.84) U1.12@6312.78,7891.88 ; v1@6507,7499 ccw(c6494.93,7499) 6503.46,7507.54 ccw(c6512,7516.07) v1@6512,7504 ; v1@6515.54,7495.46 cw(c6524.07,7486.93) 6524.07,7499 cw(c6524.07,7511.07) v1@6515.54,7502.54 ; v1@6669.39,6412.53 cw(c6660.86,6404) 6672.93,6404 cw(c6685,6404) v1@6676.47,6412.53 ; U4.64@6670.88,6399.52 ccw(c6665.92,6404.48) 6672.93,6404.48 ccw(c6679.94,6404.48) U4.64@6674.98,6399.52 ; U4.64@6672.93,6364 v1(6672.93,6416.07) ; v1@6942.46,7495.46 ccw(c6933.93,7486.93) 6933.93,7499 ccw(c6933.93,7511.07) v1@6942.46,7502.54 ; v1@6949.54,7495.46 cw(c6958.07,7486.93) 6958.07,7499 cw(c6958.07,7511.07) v1@6949.54,7502.54 ; v1@7480.46,7495.46 ccw(c7471.93,7486.93) 7471.93,7499 ccw(c7471.93,7511.07) v1@7480.46,7502.54
  BottomLayer w6: v1@6082.79,6771.87 ccw(c6074.26,6780.4) 6086.33,6780.4 ccw(c6098.4,6780.4) v1@6089.87,6771.87 ; v1(6086.33,6768.33) 6086.33,6882 6244,7039.67 6244,7230 6271,7257 ; 6270.78,7257.22 v1(6512,7499) ; v1@6507,7498.99 cw(c6494.93,7498.98) 6503.47,7490.45 cw(c6512.02,7481.93) v1@6512.01,7494 ; v1@6669.39,6419.61 ccw(c6660.86,6428.14) 6672.93,6428.14 ccw(c6685,6428.14) v1@6676.47,6419.61 ; v1(6672.93,6416.07) 6672.93,6691.07 6493,6871 6493,7046 v1(6946,7499) ; v1@6941,7499 cw(c6928.93,7499) 6937.46,7490.46 cw(c6946,7481.93) v1@6946,7494 ; v1(7484,7499) 7499,7514 R73.8@7555.84,7514 ; v1@7484,7504 ccw(c7484,7516.07) 7492.54,7507.54 ccw(c7501.07,7499) v1@7489,7499 ; R73.8@7543.1,7509.76 ccw(c7532.86,7499.51) 7532.86,7514 ccw(c7532.86,7528.49) R73.8@7543.1,7518.24
EA11: R36.8 U1.5 U2.18 U4.65 | length 4027.7
  TopLayer w6: U2.18@5966,6748.65 v1(6066.65,6748.65) ; U2.18@6001.52,6746.59 cw(c6006.48,6741.63) 6006.48,6748.65 cw(c6006.48,6755.66) U2.18@6001.52,6750.7 ; v1@6063.11,6745.11 ccw(c6054.57,6736.57) 6054.57,6748.65 ccw(c6054.57,6760.72) v1@6063.11,6752.18 ; U1.5@6274.31,7752.03 6340.97,7752.03 6408,7685 6408,7438 6485,7361 6522,7361 ; U1.5@6312.78,7749.98 cw(c6317.74,7745.02) 6317.74,7752.03 cw(c6317.74,7759.05) U1.5@6312.78,7754.09 ; v1(6343.82,7360.82) 6522,7360.85 6835,7360.9 R36.8@7555.84,7361 ; v1@6347.36,7357.29 cw(c6355.9,7348.76) 6355.9,7360.83 cw(c6355.89,7372.9) v1@6347.36,7364.36 ; v1@6689.08,6431.85 cw(c6680.54,6423.31) 6692.61,6423.31 cw(c6704.69,6423.31) v1@6696.15,6431.85 ; U4.65@6690.56,6399.52 ccw(c6685.6,6404.48) 6692.61,6404.48 ccw(c6699.63,6404.48) U4.65@6694.67,6399.52 ; U4.65@6692.61,6364 v1(6692.61,6435.39) ; 6822.68,7360.89 ccw(c6822.68,7373.32) v1@6831.46,7364.54 ; 6823.18,7360.89 cw(c6823.18,7349.18) v1@6831.46,7357.46 ; v1@6838.54,7357.46 cw(c6846.82,7349.18) 6846.82,7360.9 ; v1@6838.54,7364.54 ccw(c6847.32,7373.32) 6847.32,7360.9 ; R36.8@7543.1,7356.76 ccw(c7532.86,7346.52) 7532.86,7361 ccw(c7532.85,7375.49) R36.8@7543.1,7365.24
  BottomLayer w6: v1@6063.11,6752.18 ccw(c6054.57,6760.72) 6066.65,6760.72 ccw(c6078.72,6760.72) v1@6070.18,6752.18 ; v1(6066.65,6748.65) 6066.65,6883.65 6229,7046 6229,7246 v1(6343.82,7360.82) ; v1@6338.82,7360.82 cw(c6326.75,7360.82) 6335.29,7352.29 cw(c6343.82,7343.75) v1@6343.82,7355.82 ; v1@6689.08,6438.92 ccw(c6680.54,6447.46) 6692.61,6447.46 ccw(c6704.69,6447.46) v1@6696.15,6438.92 ; v1(6692.61,6435.39) 6692.61,6697.39 6510,6880 6510,7036 v1(6835,7361) ; v1@6830,7361 cw(c6817.93,7361) 6826.46,7352.46 cw(c6835,7343.93) v1@6835,7356
EA12: R36.7 U1.7 U2.8 U4.66 | length 4295.5
  TopLayer w6: U2.8@5966,6551.8 v1(6127.8,6551.8) ; U2.8@6001.52,6549.74 cw(c6006.48,6544.78) 6006.48,6551.8 cw(c6006.48,6558.81) U2.8@6001.52,6553.85 ; v1@6124.26,6548.26 ccw(c6115.72,6539.72) 6115.72,6551.8 ccw(c6115.72,6563.87) v1@6124.26,6555.33 ; U1.7@6274.31,7791.4 6345.6,7791.4 6442,7695 6442,7455 6500,7397 R36.7@7555.84,7397 ; U1.7@6312.78,7789.35 cw(c6317.74,7784.39) 6317.74,7791.4 cw(c6317.74,7798.42) U1.7@6312.78,7793.46 ; v1@6597.46,7393.46 ccw(c6588.93,7384.93) 6588.93,7397 ccw(c6588.93,7409.07) v1@6597.46,7400.54 ; v1@6604.54,7393.46 cw(c6613.07,7384.93) 6613.07,7397 cw(c6613.07,7409.07) v1@6604.54,7400.54 ; v1@6708.76,6413.16 cw(c6700.23,6404.63) 6712.3,6404.63 cw(c6724.37,6404.63) v1@6715.84,6413.16 ; U4.66@6710.25,6399.52 ccw(c6705.29,6404.48) 6712.3,6404.48 ccw(c6719.31,6404.48) U4.66@6714.35,6399.52 ; U4.66@6712.3,6364 v1(6712.3,6416.7) ; v1@6895.46,7393.46 ccw(c6886.93,7384.93) 6886.93,7397 ccw(c6886.93,7409.07) v1@6895.46,7400.54 ; v1@6902.54,7393.46 cw(c6911.07,7384.93) 6911.07,7397 cw(c6911.07,7409.07) v1@6902.54,7400.54 ; R36.7@7543.1,7392.76 ccw(c7532.86,7382.51) 7532.86,7397 ccw(c7532.86,7411.49) R36.7@7543.1,7401.24
  BottomLayer w6: v1(6127.8,6551.8) 6255,6679 6255,6888 6337,6970 6337,7131 6364,7158 ; v1@6127.8,6556.8 ccw(c6127.8,6568.87) 6136.33,6560.33 ccw(c6144.87,6551.8) v1@6132.8,6551.8 ; 6363.31,7158.68 v1(6601,7397) ; v1@6596,7396.99 cw(c6583.93,7396.98) 6592.48,7388.45 cw(c6601.02,7379.93) v1@6601.01,7392 ; v1@6708.76,6420.24 ccw(c6700.23,6428.77) 6712.3,6428.77 ccw(c6724.37,6428.77) v1@6715.84,6420.24 ; v1(6712.3,6416.7) 6712.3,6706.7 6529,6890 6529,7027 v1(6899,7397) ; v1@6894,7397 cw(c6881.93,7397) 6890.46,7388.46 cw(c6899,7379.93) v1@6899,7392
EA13: R36.6 U2.7 U4.24 | length 3188.2
  TopLayer w6: U2.7@5966,6532.11 v1(6149.11,6532.11) ; U2.7@6001.52,6530.06 cw(c6006.48,6525.1) 6006.48,6532.11 cw(c6006.48,6539.12) U2.7@6001.52,6534.16 ; v1@6145.57,6528.57 ccw(c6137.04,6520.04) 6137.04,6532.11 ccw(c6137.04,6544.18) v1@6145.57,6535.65 ; v1@6649.71,6912.71 cw(c6641.17,6904.17) 6653.24,6904.17 cw(c6665.32,6904.17) v1@6656.78,6912.71 ; U4.24@6651.19,6869.52 ccw(c6646.23,6874.48) 6653.24,6874.48 ccw(c6660.26,6874.48) U4.24@6655.3,6869.52 ; U4.24@6653.24,6834 v1(6653.24,6916.24) ; v1(6664,7433) R36.6@7555.84,7433 ; v1@6667.54,7429.46 cw(c6676.07,7420.93) 6676.07,7433 cw(c6676.07,7445.07) v1@6667.54,7436.54 ; v1@7095.46,7429.46 ccw(c7086.93,7420.93) 7086.93,7433 ccw(c7086.93,7445.07) v1@7095.46,7436.54 ; v1@7102.54,7429.46 cw(c7111.07,7420.93) 7111.07,7433 cw(c7111.07,7445.07) v1@7102.54,7436.54 ; R36.6@7543.1,7428.76 ccw(c7532.86,7418.51) 7532.86,7433 ccw(c7532.86,7447.49) R36.6@7543.1,7437.24
  BottomLayer w6: v1(6149.11,6532.11) 6271,6654 6271,6874 6355,6958 6355,7124 v1(6664,7433) ; v1@6149.11,6537.11 ccw(c6149.11,6549.18) 6157.65,6540.65 ccw(c6166.18,6532.11) v1@6154.11,6532.11 ; v1@6649.71,6919.78 ccw(c6641.17,6928.32) 6653.24,6928.32 ccw(c6665.32,6928.32) v1@6656.78,6919.78 ; v1(6653.24,6916.24) 6653.24,6987.24 v1(7099,7433) ; v1@6659,7433 cw(c6646.93,7433) 6655.46,7424.46 cw(c6664,7415.93) v1@6664,7428 ; v1@7094,7433 cw(c7081.93,7433) 7090.46,7424.46 cw(c7099,7415.93) v1@7099,7428
EA14: R36.5 U2.6 U4.21 | length 3279.8
  TopLayer w6: U2.6@5966,6512.43 v1(6176.43,6512.43) ; U2.6@6001.52,6510.37 cw(c6006.48,6505.41) 6006.48,6512.43 cw(c6006.48,6519.44) U2.6@6001.52,6514.48 ; v1@6172.89,6508.89 ccw(c6164.35,6500.35) 6164.35,6512.43 ccw(c6164.35,6524.5) v1@6172.89,6515.96 ; v1@6708.76,6886.76 cw(c6700.23,6878.23) 6712.3,6878.23 cw(c6724.37,6878.23) v1@6715.84,6886.76 ; U4.21@6710.25,6869.52 ccw(c6705.29,6874.48) 6712.3,6874.48 ccw(c6719.31,6874.48) U4.21@6714.35,6869.52 ; U4.21@6712.3,6834 v1(6712.3,6890.3) ; v1(6732,7469) R36.5@7555.84,7469 ; v1@6735.54,7465.46 cw(c6744.07,7456.93) 6744.07,7469 cw(c6744.07,7481.07) v1@6735.54,7472.54 ; v1@7210.46,7465.46 ccw(c7201.93,7456.93) 7201.93,7469 ccw(c7201.93,7481.07) v1@7210.46,7472.54 ; v1@7217.54,7465.46 cw(c7226.07,7456.93) 7226.07,7469 cw(c7226.07,7481.07) v1@7217.54,7472.54 ; R36.5@7543.1,7464.76 ccw(c7532.86,7454.51) 7532.86,7469 ccw(c7532.86,7483.49) R36.5@7543.1,7473.24
  BottomLayer w6: v1(6176.43,6512.43) 6291,6627 6291,6866 6371,6946 6371,7110 6415,7154 ; v1@6176.43,6517.43 ccw(c6176.43,6529.5) 6184.96,6520.96 ccw(c6193.5,6512.43) v1@6181.43,6512.43 ; 6415.33,7153.66 v1(6732,7469) ; v1@6708.76,6893.84 ccw(c6700.23,6902.37) 6712.3,6902.37 ccw(c6724.37,6902.37) v1@6715.84,6893.84 ; v1(6712.3,6890.3) 6712.3,6967.3 v1(7214,7469) ; v1@6727,7469.01 cw(c6714.93,7469.04) 6723.45,7460.48 cw(c6731.96,7451.93) v1@6731.99,7464 ; v1@7209,7469 cw(c7196.93,7469) 7205.46,7460.46 cw(c7214,7451.93) v1@7214,7464
EA15: R37.8 U2.5 U4.22 | length 3415.4
  TopLayer w6: U2.5@5966,6492.74 v1(6201.74,6492.74) ; U2.5@6001.52,6490.69 cw(c6006.48,6485.73) 6006.48,6492.74 cw(c6006.48,6499.75) U2.5@6001.52,6494.79 ; v1@6198.2,6489.2 ccw(c6189.67,6480.67) 6189.67,6492.74 ccw(c6189.67,6504.81) v1@6198.2,6496.28 ; v1@6689.08,6909.08 cw(c6680.54,6900.54) 6692.61,6900.54 cw(c6704.69,6900.54) v1@6696.15,6909.08 ; U4.22@6690.56,6869.52 ccw(c6685.6,6874.48) 6692.61,6874.48 ccw(c6699.63,6874.48) U4.22@6694.67,6869.52 ; U4.22@6692.61,6834 v1(6692.61,6912.61) ; v1(6838,7534) R37.8@7555.84,7534 ; v1@6841.54,7530.46 cw(c6850.07,7521.93) 6850.07,7534 cw(c6850.07,7546.07) v1@6841.54,7537.54 ; v1@7248.46,7530.46 ccw(c7239.93,7521.93) 7239.93,7534 ccw(c7239.93,7546.07) v1@7248.46,7537.54 ; v1@7255.54,7530.46 cw(c7264.07,7521.93) 7264.07,7534 cw(c7264.07,7546.07) v1@7255.54,7537.54 ; R37.8@7543.1,7529.76 ccw(c7532.86,7519.51) 7532.86,7534 ccw(c7532.86,7548.49) R37.8@7543.1,7538.24
  BottomLayer w6: v1(6201.74,6492.74) 6310,6601 6310,6734 6345,6769 6345,6889 6392,6936 6392,7109 6542.23,7259.23 6562.23,7259.23 v1@6836,7533 ; v1@6201.74,6497.74 ccw(c6201.74,6509.81) 6210.28,6501.28 ccw(c6218.81,6492.74) v1@6206.74,6492.74 ; v1@6689.08,6916.15 ccw(c6680.54,6924.69) 6692.61,6924.69 ccw(c6704.69,6924.69) v1@6696.15,6916.15 ; v1(6692.61,6912.61) 6692.61,6974.61 v1(7252,7534) ; 6827.76,7524.76 cw(c6838,7514.51) v1@6838,7529 ; 6830.17,7527.17 ccw(c6823.34,7534) v1@6833,7534 ; v1@7247,7534 cw(c7234.93,7534) 7243.46,7525.46 cw(c7252,7516.93) v1@7252,7529
EA16: R37.7 U2.4 U4.23 | length 3856.1
  TopLayer w6: v1(5848,6474) U2.4@5966,6473.06 ; v1@5851.51,6470.44 cw(c5859.97,6461.83) 5860.07,6473.9 cw(c5860.17,6485.97) v1@5851.56,6477.51 ; 5924.88,6473.38 cw(c5924.81,6465.46) U2.4@5930.46,6471.02 ; 5926.17,6473.37 ccw(c5926.22,6479.47) U2.4@5930.5,6475.13 ; v1@6669.39,6889.39 cw(c6660.86,6880.86) 6672.93,6880.86 cw(c6685,6880.86) v1@6676.47,6889.39 ; U4.23@6670.88,6869.52 ccw(c6665.92,6874.48) 6672.93,6874.48 ccw(c6679.94,6874.48) U4.23@6674.98,6869.52 ; U4.23@6672.93,6834 v1(6672.93,6892.93) ; v1@7136,7645 cw(c7136,7632.93) 7144.54,7641.46 cw(c7153.07,7650) v1@7141,7650 ; v1(7136,7650) 7216,7570 R37.7@7555.84,7570 ; v1@7258.46,7566.46 ccw(c7249.93,7557.93) 7249.93,7570 ccw(c7249.93,7582.07) v1@7258.46,7573.54 ; v1@7265.54,7566.46 cw(c7274.07,7557.93) 7274.07,7570 cw(c7274.07,7582.07) v1@7265.54,7573.54 ; R37.7@7543.1,7565.76 ccw(c7532.86,7555.51) 7532.86,7570 ccw(c7532.86,7584.49) R37.7@7543.1,7574.24
  BottomLayer w6: v1@5844.46,6477.54 ccw(c5835.93,6486.07) 5848,6486.07 ccw(c5860.07,6486.07) v1@5851.54,6477.54 ; v1(5848,6474) 5848,6867 6152,7171 6152,7315 6487,7650 v1(7136,7650) ; v1@6669.39,6896.47 ccw(c6660.86,6905) 6672.93,6905 ccw(c6685,6905) v1@6676.47,6896.47 ; v1(6672.93,6892.93) 6672.93,6980.93 v1(7262,7570) ; v1@7132.46,7646.46 ccw(c7123.93,7637.93) 7123.93,7650 ccw(c7123.93,7662.07) v1@7132.46,7653.54 ; v1@7257,7570 cw(c7244.93,7570) 7253.46,7561.46 cw(c7262,7552.93) v1@7262,7565
EA17: R74.5 U2.3 | length 2519.3
  TopLayer w6: U2.3@5966,6453.37 v1(6043.96,6453.37) ; U2.3@6001.52,6451.32 cw(c6006.48,6446.36) 6006.48,6453.37 cw(c6006.48,6460.38) U2.3@6001.52,6455.42 ; v1@6040.42,6449.83 ccw(c6031.89,6441.3) 6031.89,6453.37 ccw(c6031.89,6465.44) v1@6040.42,6456.91
  BottomLayer w6: v1@6040.42,6456.91 ccw(c6031.89,6465.44) 6043.96,6465.44 ccw(c6056.03,6465.44) v1@6047.5,6456.91 ; v1(6043.96,6453.37) 6043.96,6886 6216.46,7058.5 6216.46,7269.46 6505,7558 7208,7558 7240,7590 7409,7590 7433,7566 R74.5@7555.84,7566 ; R74.5@7543.1,7561.76 ccw(c7532.86,7551.51) 7532.86,7566 ccw(c7532.86,7580.49) R74.5@7543.1,7570.24
EA18: R74.8 U2.2 | length 2686.7
  TopLayer w6: v1(5902.31,6433.69) U2.2@5966,6433.69 ; v1@5905.85,6430.15 cw(c5914.39,6421.61) 5914.39,6433.69 cw(c5914.39,6445.76) v1@5905.85,6437.22 ; U2.2@5930.48,6431.63 ccw(c5925.52,6426.67) 5925.52,6433.69 ccw(c5925.52,6440.7) U2.2@5930.48,6435.74
  BottomLayer w6: v1@5897.32,6433.69 ccw(c5885.24,6433.69) 5893.78,6442.22 ccw(c5902.31,6450.76) v1@5902.31,6438.68 ; v1(5902.31,6433.69) 5867,6469 5867,6858 6169.54,7160.54 6169.54,7306.54 6486,7623 7152,7623 7203,7674 R74.8@7555.84,7674 ; R74.8@7543.1,7669.76 ccw(c7532.86,7659.51) 7532.86,7674 ccw(c7532.86,7688.49) R74.8@7543.1,7678.24
EA19: R20.2 R37.6 U2.1 | length 3111.4
  TopLayer w6: v1(5853,6414) 6052.54,6414 R20.2@6086.54,6380 ; v1@5856.54,6410.46 cw(c5865.07,6401.93) 5865.07,6414 cw(c5865.07,6426.07) v1@5856.54,6417.54 ; U2.1@5930.48,6411.95 ccw(c5925.52,6406.99) 5925.52,6414 ccw(c5925.52,6421.01) U2.1@5930.48,6416.05 ; U2.1@6001.52,6411.95 cw(c6006.48,6406.99) 6006.48,6414 cw(c6006.48,6421.01) U2.1@6001.52,6416.05 ; 6054.69,6411.84 cw(c6022.85,6380) R20.2@6067.88,6380 ; 6059.44,6407.09 ccw(c6084.57,6432.21) R20.2@6084.57,6396.69 ; 6064.93,6401.6 cw(c6043.33,6380) R20.2@6073.88,6380 ; R20.2@6069.69,6396.85 ccw(c6084.57,6411.73) R20.2@6084.57,6390.69 ; v1@7163,7666 cw(c7163,7653.93) 7171.54,7662.46 cw(c7180.07,7671) v1@7168,7671 ; v1(7163,7671) 7228,7606 R37.6@7555.84,7606 ; R37.6@7543.1,7601.76 ccw(c7532.86,7591.51) 7532.86,7606 ccw(c7532.86,7620.49) R37.6@7543.1,7610.24
  BottomLayer w6: v1@5848,6414 ccw(c5835.93,6414) 5844.46,6422.54 ccw(c5853,6431.07) v1@5853,6419 ; v1(5853,6414) 5829,6438 5829,6873 6134,7178 6134,7325 6480,7671 v1(7163,7671) ; v1@7159.46,7667.46 ccw(c7150.93,7658.93) 7150.93,7671 ccw(c7150.93,7683.07) v1@7159.46,7674.54
EA20: R19.1 R37.5 U2.48 | length 3816.2
  TopLayer w6: U2.48@5135.21,6411.95 ccw(c5130.25,6406.99) 5130.25,6414 ccw(c5130.25,6421.01) U2.48@5135.21,6416.05 ; U2.48@5206.24,6411.95 cw(c5211.2,6406.99) 5211.2,6414 cw(c5211.2,6421.01) U2.48@5206.24,6416.05 ; R19.1@5214.74,6351.8 ccw(c5186.25,6380.28) 5226.54,6380.28 ccw(c5266.82,6380.28) R19.1@5238.33,6351.8 ; R19.1@5218.98,6347.56 ccw(c5200.74,6365.8) 5226.54,6365.8 ccw(c5252.33,6365.8) R19.1@5234.09,6347.56 ; v1@5225.46,6919.46 ccw(c5216.93,6910.93) 5216.93,6923 ccw(c5216.93,6935.07) v1@5225.46,6926.54 ; R19.1@5226.54,6340 5226.54,6405.46 5218,6414 5118,6414 5024,6508 5024,6827 5120,6923 v1(5229,6923) ; v1@7194,7689 cw(c7194,7676.93) 7202.54,7685.46 cw(c7211.07,7694) v1@7199,7694 ; v1(7194,7694) 7246,7642 R37.5@7555.84,7642 ; R37.5@7543.1,7637.76 ccw(c7532.86,7627.51) 7532.86,7642 ccw(c7532.86,7656.49) R37.5@7543.1,7646.24
  BottomLayer w6: v1(5229,6923) 5741,6923 6055,7237 6055,7322 6427,7694 v1(7194,7694) ; v1@5232.54,6919.46 cw(c5241.07,6910.93) 5241.07,6923 cw(c5241.07,6935.07) v1@5232.54,6926.54 ; v1@7190.46,7690.46 ccw(c7181.93,7681.93) 7181.93,7694 ccw(c7181.93,7706.07) v1@7190.46,7697.54
EA21: R74.7 S1.3 U2.17 | length 4456.2
  TopLayer w6: v2@5680.05,7047.05 cw(c5668.1,7035.1) 5685,7035.1 cw(c5701.9,7035.1) v2@5689.95,7047.05 ; v2(5685,7052) 5685,6754 5710.04,6728.96 U2.17@5966,6728.96 ; v1@5882.5,6725.42 ccw(c5873.97,6716.89) 5873.97,6728.96 ccw(c5873.97,6741.03) v1@5882.5,6732.5 ; v1@5889.58,6725.42 cw(c5898.11,6716.89) 5898.11,6728.96 cw(c5898.11,6741.03) v1@5889.58,6732.5 ; U2.17@5930.48,6726.91 ccw(c5925.52,6721.95) 5925.52,6728.96 ccw(c5925.52,6735.97) U2.17@5930.48,6731.01
  BottomLayer w6: v1@5882.5,6732.5 ccw(c5873.97,6741.03) 5886.04,6741.03 ccw(c5898.11,6741.03) v1@5889.58,6732.5 ; v1(5886.04,6728.96) 5886.04,6851.04 6185,7150 6185,7298 6493,7606 7183,7606 7215,7638 R74.7@7555.84,7638 ; R74.7@7543.1,7633.76 ccw(c7532.86,7623.51) 7532.86,7638 ccw(c7532.86,7652.49) R74.7@7543.1,7642.24
  BottomLayer w8: S1.3@5001.95,6291.05 ccw(c4958.37,6334.63) 5020,6334.63 ccw(c5081.63,6334.63) S1.3@5038.05,6291.05 ; S1.3@5007.61,6285.39 ccw(c4977.68,6315.32) 5020,6315.32 ccw(c5062.32,6315.32) S1.3@5032.39,6285.39 ; S1.3@5020,6273 5020,6907 5165,7052 v2(5685,7052) ; v2@5680.76,7047.76 ccw(c5670.51,7037.51) 5670.51,7052 ccw(c5670.51,7066.49) v2@5680.76,7056.24
EA22: R74.6 S1.4 U2.16 | length 4504.9
  TopLayer w6: v1@5655.46,7022.46 cw(c5646.93,7013.93) 5659,7013.93 cw(c5671.07,7013.93) v1@5662.54,7022.46 ; v1(5659,7026) 5659,6746.27 5696,6709.27 ; 5695,6709 5966,6709.23 v1(6021.27,6709.27) ; 5925.34,6709.19 ccw(c5925.33,6716.46) U2.16@5930.48,6711.33 ; 5925.7,6709.19 cw(c5925.71,6702.44) U2.16@5930.48,6707.22 ; U2.16@6001.52,6707.22 cw(c6006.44,6702.31) 6006.43,6709.26 ; U2.16@6001.52,6711.33 ccw(c6006.52,6716.34) 6006.52,6709.26 ; v1@6017.74,6705.74 ccw(c6009.21,6697.19) 6009.2,6709.26 ccw(c6009.19,6721.34) v1@6017.74,6712.81
  BottomLayer w6: v1@6017.74,6712.81 ccw(c6009.2,6721.35) 6021.28,6721.35 ccw(c6033.35,6721.35) v1@6024.81,6712.81 ; v1(6021.27,6709.27) 6021.27,6890.27 6202,7071 6202,7287 6501,7586 7194,7586 7221,7613 7422,7613 7433,7602 R74.6@7555.84,7602 ; R74.6@7543.1,7597.76 ccw(c7532.86,7587.51) 7532.86,7602 ccw(c7532.86,7616.49) R74.6@7543.1,7606.24
  BottomLayer w8: S1.4@5020,6173 5067,6220 5067,6320 5041,6346 5041,6888 5179,7026 v1(5659,7026) ; S1.4@5020,6190.53 ccw(c5020,6232.84) 5049.92,6202.92 ccw(c5079.84,6173) S1.4@5037.53,6173 ; S1.4@5020,6198.53 ccw(c5020,6260.16) 5063.58,6216.58 ccw(c5107.16,6173) S1.4@5045.53,6173 ; v1@5656.17,7023.17 ccw(c5649.34,7016.34) 5649.34,7026 ccw(c5649.34,7035.66) v1@5656.17,7028.83
ECLKIN: R75.2 U11.H25 | length 1321.4
  TopLayer w6: U11.H25@8021.12,7109.59 v1(8039.53,7128)
  BottomLayer w6: R75.2@7413.46,7714 7688,7714 7839,7563 8070,7563 8100,7533 8100,7188.47 v1(8039.53,7128) ; R75.2@7422.99,7706.44 cw(c7441.23,7688.2) 7441.23,7714 cw(c7441.23,7739.8) R75.2@7422.99,7721.56 ; R75.2@7427.23,7702.2 cw(c7455.71,7673.72) 7455.71,7714 cw(c7455.71,7754.28) R75.2@7427.23,7725.8
ECLKOUT1: R27.2 U1.28 U4.68 | length 3719.5
  TopLayer w6: v1@5891,7099 cw(c5891,7082.1) 5902.95,7094.05 ; v1(5891,7104) 5893,7104 5986,7011 6518,7011 6576,6953 6853,6953 v1(6872,6934) R27.2@7312.54,6934 ; v1@5896,7104 ccw(c5903.24,7104) 5898.12,7098.88 ; v1(6208,8204.79) U1.28@6287.1,8204.79 ; v1@6211.54,8201.25 cw(c6220.07,8192.72) 6220.07,8204.79 cw(c6220.07,8216.86) v1@6211.54,8208.32 ; U1.28@6261.43,8202.73 ccw(c6256.47,8197.77) 6256.47,8204.79 ccw(c6256.47,8211.8) U1.28@6261.43,8206.84 ; v1@6748.13,6413.13 cw(c6739.6,6404.6) 6751.67,6404.6 cw(c6763.74,6404.6) v1@6755.21,6413.13 ; U4.68@6749.62,6399.52 ccw(c6744.66,6404.48) 6751.67,6404.48 ccw(c6758.68,6404.48) U4.68@6753.72,6399.52 ; U4.68@6751.67,6364 v1(6751.67,6416.67) ; v1@6867,6934 ccw(c6854.93,6934) 6863.46,6942.54 ccw(c6872,6951.07) v1@6872,6939 ; v1@6875.54,6930.46 cw(c6884.07,6921.93) 6884.07,6934 cw(c6884.07,6946.07) v1@6875.54,6937.54 ; R27.2@7298.77,6922.2 ccw(c7270.29,6893.72) 7270.29,6934 ccw(c7270.29,6974.28) R27.2@7298.77,6945.8 ; R27.2@7303.01,6926.44 ccw(c7284.77,6908.2) 7284.77,6934 ccw(c7284.77,6959.8) R27.2@7303.01,6941.56
  BottomLayer w6: v1(5891,7104) 6033,7246 6033,7328 6208,7503 v1(6208,8204.79) ; v1@5891,7109 ccw(c5891,7121.07) 5899.54,7112.54 ccw(c5908.07,7104) v1@5896,7104 ; v1@6204.46,8201.25 cw(c6195.93,8192.72) 6208,8192.72 cw(c6220.07,8192.72) v1@6211.54,8201.25 ; v1@6748.13,6420.21 ccw(c6739.6,6428.74) 6751.67,6428.74 ccw(c6763.74,6428.74) v1@6755.21,6420.21 ; v1(6751.67,6416.67) 6751.67,6813.67 v1(6872,6934) ; v1@6867,6934 cw(c6854.93,6934) 6863.46,6925.46 cw(c6872,6916.93) v1@6872,6929
ECLKOUT2: U1.235 U11.J23 | length 2772.5
  TopLayer w6: U1.235@6086.23,7547.22 cw(c6081.27,7542.26) 6088.28,7542.26 cw(c6095.3,7542.26) U1.235@6090.34,7547.22 ; U1.235@6088.28,7585.69 6088.28,7526.28 5952,7390 5952,7173 6037,7088 6580,7088 6607,7061 v1(7496,7061) ; v1@7492.46,7057.46 ccw(c7483.93,7048.93) 7483.93,7061 ccw(c7483.93,7073.07) v1@7492.46,7064.54 ; v1(8078.9,7128) U11.J23@8099.86,7148.96 ; U11.J23@8093.61,7148.96 cw(c8078.51,7148.96) 8089.19,7138.29 cw(c8099.86,7127.62) U11.J23@8099.86,7142.71
  BottomLayer w6: v1(7496,7061) 7697,7061 7746,7110 8060.9,7110 v1(8078.9,7128) ; v1@7499.54,7057.46 cw(c7508.07,7048.93) 7508.07,7061 cw(c7508.07,7073.07) v1@7499.54,7064.54
ED00: R40.5 U1.181 U2.29 U4.2 | length 5186.1
  TopLayer w6: U1.181@5023.24,7547.22 cw(c5018.28,7542.26) 5025.29,7542.26 cw(c5032.31,7542.26) U1.181@5027.35,7547.22 ; U1.181@5025.29,7585.69 5025.29,7433.71 5252,7207 v1(5252,6788) U2.29@5170.72,6788.02 ; U2.29@5206.24,6785.96 cw(c5211.19,6781.01) 5211.19,6788.01 cw(c5211.22,6795.04) U2.29@5206.24,6790.07 ; v1@5248.46,6784.47 ccw(c5239.93,6775.93) 5239.93,6788 ccw(c5239.93,6800.07) 5248.47,6791.54 ccw(c5239.93,6800.07) 5252,6800.07 ccw(c5264.07,6800.07) v1@5255.54,6791.54 ; U4.2@7084.26,6798.48 cw(c7079.3,6793.52) 7086.32,6793.52 cw(c7093.33,6793.52) U4.2@7088.37,6798.48 ; U4.2@7086.31,6834 7086.31,6754.69 7208,6633 7602,6633 7759,6476 v1(7917,6476) 7958,6517 R40.5@7958,6543.84 ; v1@7913.46,6472.46 ccw(c7904.93,6463.93) 7904.93,6476 ccw(c7904.93,6488.07) v1@7913.46,6479.54 ; v1@7917,6481 ccw(c7917,6493.07) 7925.54,6484.54 ccw(c7934.07,6476) v1@7922,6476 ; R40.5@7953.76,6531.1 cw(c7943.51,6520.86) 7958,6520.86 cw(c7972.49,6520.86) R40.5@7962.24,6531.1
  BottomLayer w6: v1(5252,6788) 5284.98,6788.02 5765,6308 7310,6308 7478,6476 v1(7917,6476) ; v1@5255.54,6784.47 cw(c5264.08,6775.93) 5264.07,6788.01 cw(c5264.07,6800.08) v1@5255.53,6791.54 ; v1@7913.46,6472.46 ccw(c7904.93,6463.93) 7904.93,6476 ccw(c7904.93,6488.07) v1@7913.46,6479.54
ED01: R40.6 U1.182 U2.31 U4.4 | length 5340.2
  TopLayer w6: U1.182@5042.92,7547.22 cw(c5037.96,7542.26) 5044.98,7542.26 cw(c5051.99,7542.26) U1.182@5047.03,7547.22 ; U1.182@5044.98,7585.69 5044.98,7442.02 5269,7218 v1(5269,6751) U2.31@5173.08,6751 ; U2.31@5170.72,6748.65 U2.31@5173.08,6748.65 ; U2.31@5206.24,6746.59 cw(c5216.89,6735.94) 5216.89,6751 ; v1@5265.46,6747.46 ccw(c5256.93,6738.93) 5256.93,6751 ccw(c5256.93,6763.07) 5265.46,6754.54 ccw(c5256.93,6763.07) 5269,6763.07 ccw(c5281.07,6763.07) v1@5272.54,6754.54 ; U4.4@7044.89,6798.48 cw(c7039.93,6793.52) 7046.95,6793.52 cw(c7053.96,6793.52) U4.4@7049,6798.48 ; U4.4@7046.94,6834 7046.94,6771.06 7200,6618 7592,6618 7753,6457 7938,6457 7994,6513 R40.6@7994,6543.84 ; v1@7949.5,6473.5 cw(c7937.43,6473.5) 7945.97,6464.97 cw(c7954.5,6456.43) v1@7954.5,6468.5 ; v1@7954.5,6478.5 ccw(c7954.5,6490.57) 7963.04,6482.04 ccw(c7971.57,6473.5) v1@7959.5,6473.5 ; R40.6@7989.76,6531.1 cw(c7979.51,6520.86) 7994,6520.86 cw(c8008.49,6520.86) R40.6@7998.24,6531.1
  BottomLayer w6: v1(5269,6751) 5303,6751 5761,6293 7318,6293 7478,6453 7934,6453 v1(7954.5,6473.5) ; v1@5272.54,6747.46 cw(c5281.07,6738.93) 5281.07,6751 cw(c5281.07,6763.07) v1@5272.54,6754.54 ; v1@7949.5,6473.5 cw(c7937.43,6473.5) 7945.97,6464.97 cw(c7954.5,6456.43) v1@7954.5,6468.5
